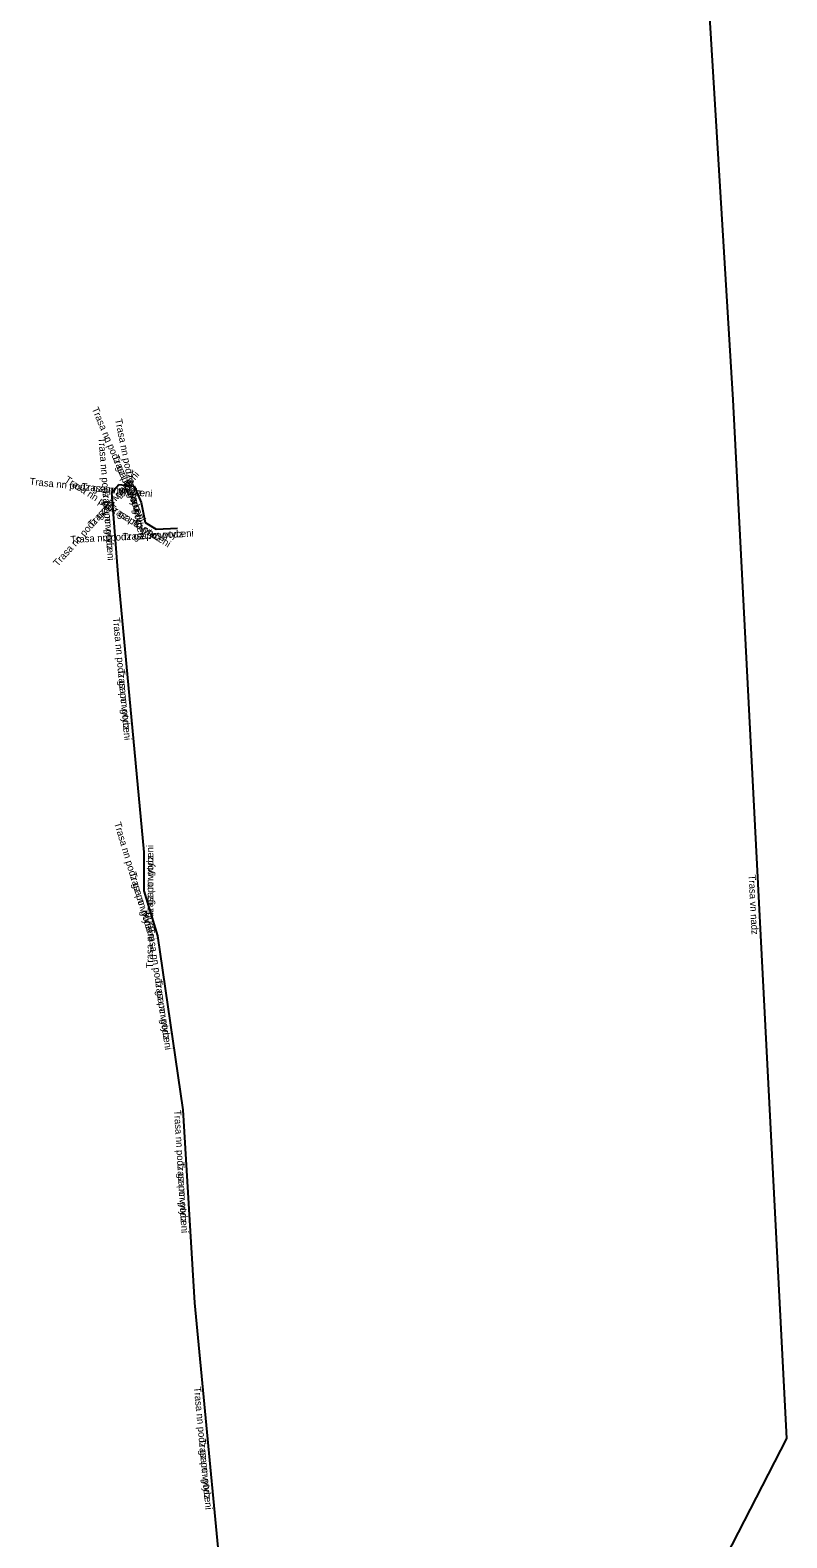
# Model space of a CAD drawing. Extents: x -632208 to -631919, y -1083193 to -1082791.
# Drawn here: x -632102.3 to -632049, y -1083098.4 to -1082992 of the extents above; entities that cross this region are included whole.
import ezdxf

# ---------------------------------------------------------------- set-up
doc = ezdxf.new("R2010")
doc.units = 0
for name, color, linetype in [('Popiskový text - Ostatní atributy Trasy', 7, 'Continuous'), ('Spojnice NN', 7, 'Continuous'), ('Spojnice VN', 7, 'Continuous')]:
    doc.layers.add(name, color=color, linetype=linetype)

msp = doc.modelspace()

# ---------------------------------------------------------------- linework, layer by layer
at = {"layer": 'Spojnice NN'}
for points in [[(-632096.57, -1083024.63), (-632096.07, -1083024.07)], [(-632096.57, -1083024.63), (-632096.07, -1083024.07)], [(-632096.07, -1083024.07), (-632094.99, -1083024.18)], [(-632096.07, -1083024.07), (-632094.99, -1083024.18)], [(-632094.99, -1083024.18), (-632094.5, -1083025.34)], [(-632094.99, -1083024.18), (-632094.5, -1083025.34)], [(-632096.13, -1083030.41), (-632096.57, -1083024.63)], [(-632096.13, -1083030.41), (-632096.57, -1083024.63)], [(-632094.5, -1083025.34), (-632094.22, -1083026.73)], [(-632094.5, -1083025.34), (-632094.22, -1083026.73)], [(-632094.22, -1083026.73), (-632093.45, -1083027.22)], [(-632094.22, -1083026.73), (-632093.45, -1083027.22)], [(-632093.45, -1083027.22), (-632091.94, -1083027.14)], [(-632093.45, -1083027.22), (-632091.94, -1083027.14)], [(-632094.29, -1083050), (-632096.13, -1083030.41)], [(-632094.29, -1083050), (-632096.13, -1083030.41)], [(-632094.3, -1083052.72), (-632094.29, -1083050)], [(-632094.3, -1083052.72), (-632094.29, -1083050)], [(-632093.34, -1083055.9), (-632094.3, -1083052.72)], [(-632093.34, -1083055.9), (-632094.3, -1083052.72)], [(-632091.54, -1083068.18), (-632093.34, -1083055.9)], [(-632091.54, -1083068.18), (-632093.34, -1083055.9)], [(-632090.71, -1083081.78), (-632091.54, -1083068.18)], [(-632090.71, -1083081.78), (-632091.54, -1083068.18)], [(-632088.29, -1083107.18), (-632090.71, -1083081.78)], [(-632088.29, -1083107.18), (-632090.71, -1083081.78)]]:
    msp.add_lwpolyline(points, dxfattribs=at)
at = {"layer": 'Spojnice VN'}
for points in [[(-632052.75, -1083018.08), (-632057.48, -1082940.51)], [(-632048.97, -1083091.35), (-632052.75, -1083018.08)], [(-632078.02, -1083147.88), (-632048.97, -1083091.35)]]:
    msp.add_lwpolyline(points, dxfattribs=at)

# ---------------------------------------------------------------- texts
at = {"layer": 'Popiskový text - Ostatní atributy Trasy'}
for s, rotation, p in [('Trasa nn podz gz po vytyceni', 292.8999, (-632098, -1083018.72)), ('Trasa nn podz gz po vytyceni', 281.3892, (-632096.35, -1083019.47)), ('Trasa nn podz gz po vytyceni', 274.3532, (-632097.52, -1083020.76)), ('Trasa nn podz', 292.8999, (-632096.57, -1083022.11)), ('Trasa nn podz gz po vytyceni', 48.2397, (-632100.39, -1083029.88)), ('Trasa nn podz', 281.3892, (-632095.62, -1083023.08)), ('Trasa nn podz gz po vytyceni', 354.1844, (-632102.39, -1083024.08)), ('Trasa nn podz gz po vytyceni', 327.5288, (-632099.95, -1083023.85)), ('Trasa nn podz', 354.1844, (-632098.73, -1083024.45)), ('Trasa nn podz', 48.2397, (-632097.93, -1083027.13)), ('Trasa nn podz', 274.3532, (-632097.24, -1083024.43)), ('Trasa nn podz', 327.5288, (-632096.84, -1083025.83)), ('Trasa nn podz gz po vytyceni', 3.0327, (-632099.48, -1083028.19)), ('Trasa nn podz', 3.0327, (-632095.8, -1083028)), ('Trasa nn podz gz po vytyceni', 275.3658, (-632096.5, -1083033.46)), ('Trasa nn podz', 275.3658, (-632096.15, -1083037.13)), ('Trasa nn podz gz po vytyceni', 286.7984, (-632096.42, -1083047.96)), ('Trasa nn podz gz po vytyceni', 89.7894, (-632093.67, -1083058.19)), ('Trasa nn podz', 89.7894, (-632093.66, -1083054.51)), ('Trasa nn podz', 286.7984, (-632095.35, -1083051.48)), ('Trasa vn nadz', 272.9534, (-632051.67, -1083051.6)), ('Trasa nn podz gz po vytyceni', 278.339, (-632094.07, -1083055.37)), ('Trasa nn podz', 278.339, (-632093.54, -1083059.02)), ('Trasa nn podz gz po vytyceni', 273.4924, (-632092.19, -1083068.2)), ('Trasa nn podz', 273.4924, (-632091.97, -1083071.88)), ('Trasa nn podz gz po vytyceni', 275.4425, (-632090.79, -1083087.74)), ('Trasa nn podz', 275.4425, (-632090.45, -1083091.41))]:
    msp.add_text(s, height=0.5, rotation=rotation, dxfattribs=at).set_placement(p)

doc.saveas('drawing.dxf')
